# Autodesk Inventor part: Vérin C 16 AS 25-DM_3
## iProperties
Shininess: 20.0
Angle Display Precision: 2
Document Length Units: 11269
Document Angle Units: 11279
Document Time Units: 11290
Document Mass Units: 11283
Document Length Units Precision: 3
Document Angle Units Precision: 2
Created: 2002-02
Part Number: Vérin C 16 AS 25-DM_3
Material: Par défaut
Document SubType Name: Modélisation
Designer: Administrateur
Density: 0.0
Volumn: 0.0
Area: 0.0
PropertySet Name: Model Information
Control State: 0
Master: False
Checked Out: False
Author: Administrateur
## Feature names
1. Base1
